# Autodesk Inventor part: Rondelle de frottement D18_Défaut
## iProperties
Shininess: 64.0
Length Units: 11269
Angle Units: 11279
Time Units: 11290
Mass Units: 11283
Length Display Precision: 3
Angle Display Precision: 2
Compacted: True
Part Number: Rondelle de frottement D18_Défaut
Document SubType Name: Modeling
Created: 2006-01
Material: Par défaut
Designer: Fricot
Density: 0.0
Volumn: 0.0
Area: 0.0
PropertySet Name: Model Information
Control State: 0
Master: False
Checked Out: False
Author: Fricot
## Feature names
1. Base1
